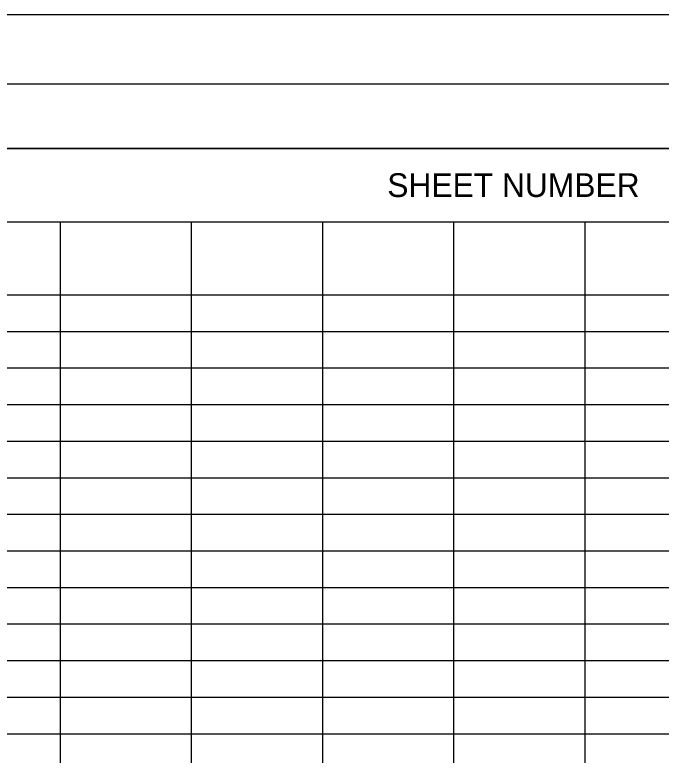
# Model space of a CAD drawing. Extents: x 0 to 34, y 0 to 22.
# Drawn here: x 4.69 to 9.38, y 16.63 to 22 of the extents above; entities that cross this region are included whole.
import ezdxf

# ---------------------------------------------------------------- set-up
doc = ezdxf.new("R2010")
doc.units = 0
for name, color, linetype in [('Default', 7, 'Continuous'), ('SH_Border', 7, 'Continuous'), ('SH_Cut_Line', 7, 'Continuous')]:
    doc.layers.add(name, color=color, linetype=linetype)

msp = doc.modelspace()

# ---------------------------------------------------------------- linework, layer by layer
at = {"layer": 'Default'}
for p, q in [((2.1608, 21.0301), (31.052, 21.0301)), ((2.1608, 20.4997), (15.4832, 20.4997)), ((5.0156, 20.4997), (5.0156, 6.4441)), ((5.9672, 20.4997), (5.9672, 6.4441)), ((6.9188, 20.4997), (6.9188, 6.4441)), ((7.8704, 20.4997), (7.8704, 6.4441)), ((8.822, 20.4997), (8.822, 6.4441)), ((2.1608, 19.9693), (31.052, 19.9693)), ((2.1608, 19.7041), (31.052, 19.7041)), ((2.1608, 19.4389), (31.052, 19.4389)), ((2.1608, 19.1737), (31.052, 19.1737)), ((2.1608, 18.9085), (31.052, 18.9085)), ((2.1608, 18.6433), (31.052, 18.6433)), ((2.1608, 18.3781), (31.052, 18.3781)), ((2.1608, 18.1129), (31.052, 18.1129)), ((2.1608, 17.8477), (31.052, 17.8477)), ((2.1608, 17.5825), (31.052, 17.5825)), ((2.1608, 17.3173), (31.052, 17.3173)), ((2.1608, 17.0521), (31.052, 17.0521)), ((2.1608, 16.7869), (31.052, 16.7869))]:
    msp.add_line(p, q, dxfattribs=at)
msp.add_lwpolyline([(2.1608, 21.0301), (12.098, 21.0301), (12.098, 21.0301), (2.1608, 21.0301)], close=True, dxfattribs=at)
msp.add_lwpolyline([(2.1608, 21.0301), (12.098, 21.0301), (12.098, 21.0301), (2.1608, 21.0301)], close=True, dxfattribs=at)
msp.add_lwpolyline([(2.1608, 21.0301), (12.098, 21.0301), (12.098, 21.0301), (2.1608, 21.0301)], close=True, dxfattribs=at)
msp.add_lwpolyline([(2.1608, 21.0301), (12.098, 21.0301), (12.098, 21.0301), (2.1608, 21.0301)], close=True, dxfattribs=at)
msp.add_lwpolyline([(2.1608, 21.0301), (12.098, 21.0301), (12.098, 21.0301), (2.1608, 21.0301)], close=True, dxfattribs=at)
msp.add_lwpolyline([(2.1608, 21.0301), (12.098, 21.0301), (12.098, 21.0301), (2.1608, 21.0301)], close=True, dxfattribs=at)
msp.add_lwpolyline([(2.1608, 21.0301), (12.098, 21.0301), (12.098, 21.0301), (2.1608, 21.0301)], close=True, dxfattribs=at)
msp.add_lwpolyline([(2.1608, 21.0301), (12.098, 21.0301), (12.098, 21.0301), (2.1608, 21.0301)], close=True, dxfattribs=at)
msp.add_lwpolyline([(2.1608, 21.0301), (12.098, 21.0301), (12.098, 21.0301), (2.1608, 21.0301)], close=True, dxfattribs=at)
msp.add_lwpolyline([(2.1608, 21.0301), (12.098, 21.0301), (12.098, 21.0301), (2.1608, 21.0301)], close=True, dxfattribs=at)
msp.add_lwpolyline([(2.1608, 21.0301), (12.098, 21.0301), (12.098, 21.0301), (2.1608, 21.0301)], close=True, dxfattribs=at)
msp.add_lwpolyline([(2.1608, 21.0301), (12.098, 21.0301), (12.098, 21.0301), (2.1608, 21.0301)], close=True, dxfattribs=at)
msp.add_lwpolyline([(2.1608, 21.0301), (12.098, 21.0301), (12.098, 21.0301), (2.1608, 21.0301)], close=True, dxfattribs=at)
msp.add_lwpolyline([(2.1608, 21.0301), (12.098, 21.0301), (12.098, 21.0301), (2.1608, 21.0301)], close=True, dxfattribs=at)
msp.add_lwpolyline([(2.1608, 21.0301), (12.098, 21.0301), (12.098, 21.0301), (2.1608, 21.0301)], close=True, dxfattribs=at)
msp.add_lwpolyline([(2.1608, 21.0301), (12.098, 21.0301), (12.098, 21.0301), (2.1608, 21.0301)], close=True, dxfattribs=at)
msp.add_lwpolyline([(2.1608, 21.0301), (12.098, 21.0301), (12.098, 21.0301), (2.1608, 21.0301)], close=True, dxfattribs=at)
msp.add_lwpolyline([(2.1608, 21.0301), (12.098, 21.0301), (12.098, 21.0301), (2.1608, 21.0301)], close=True, dxfattribs=at)
msp.add_lwpolyline([(2.1608, 21.0301), (12.098, 21.0301), (12.098, 21.0301), (2.1608, 21.0301)], close=True, dxfattribs=at)
msp.add_lwpolyline([(2.1608, 21.0301), (12.098, 21.0301), (12.098, 21.0301), (2.1608, 21.0301)], close=True, dxfattribs=at)
at = {"layer": 'SH_Border'}
msp.add_lwpolyline([(1.5, 21.5), (33.5, 21.5), (33.5, 0.5), (1.5, 0.5)], close=True, dxfattribs=at)
at = {"layer": 'SH_Cut_Line'}
msp.add_lwpolyline([(0, 0), (34, 0), (34, 22), (0, 22)], close=True, dxfattribs=at)

# ---------------------------------------------------------------- texts
at = {"layer": 'Default'}
msp.add_text('SHEET NUMBER', height=0.172224, dxfattribs=at).set_placement((7.3892, 20.6788))

doc.saveas('drawing.dxf')
